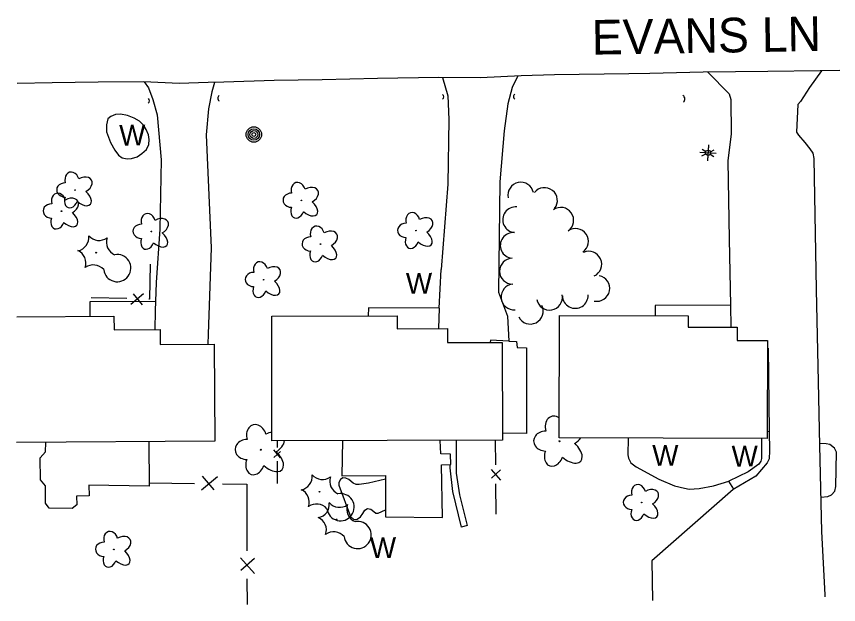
# Model space of a CAD drawing. Extents: x 588843 to 2552415, y 180129 to 269402.
# Drawn here: x 593448.9 to 593686.1, y 188818.1 to 188987.9 of the extents above; entities that cross this region are included whole.
import ezdxf

# ---------------------------------------------------------------- set-up
doc = ezdxf.new("R2010")
doc.units = 0
for name, color, linetype in [('Default', 7, 'Continuous'), ('E_BLD', 7, 'Continuous'), ('E_BLD_HvyDash', 7, 'Continuous'), ('E_DRN', 7, 'Continuous'), ('E_DWY', 7, 'Continuous'), ('E_FEN_P', 7, 'Continuous'), ('E_LAND_TreeLine_P', 7, 'Continuous'), ('E_LAND_Vegetation', 7, 'Continuous'), ('E_MISCPROP', 7, 'Continuous'), ('E_MISCPROP_ShtDash', 7, 'Continuous'), ('E_MISCPROP_YardLight', 7, 'Continuous'), ('E_PATH_Sidewalk', 7, 'Continuous'), ('E_RDWY', 7, 'Continuous'), ('E_RDWY_Text', 7, 'Continuous'), ('E_WAL', 7, 'Continuous'), ('E_WAL_Text', 7, 'Continuous')]:
    doc.layers.add(name, color=color, linetype=linetype)

# ---------------------------------------------------------------- blocks, each defined once
blk = doc.blocks.new('POLE')
at = {"layer": 'Default'}
for radius in [4.46, 3.35, 2.23, 1.12]:
    blk.add_circle((0, 0), radius, dxfattribs=at)
blk = doc.blocks.new('CULV2')
at = {"layer": 'E_DRN'}
blk.add_arc((19.7, 14.8), 24.6, 216.8699, 323.1301, dxfattribs=at)
blk = doc.blocks.new('W_29')
at = {"layer": 'E_WAL_Text'}
blk.add_text('W', height=12, dxfattribs=at).set_placement((-4.46, -6))
blk = doc.blocks.new('CTRE')
at = {"layer": 'Default'}
blk.add_circle((0, 0), 0.223, dxfattribs=at)
for centre, start, end in [((-11.97, 8.96), 280.2067, 5.9716), ((1.81, 14.92), 220.2113, 305.9762), ((13.83, 5.89), 160.2113, 245.9762), ((-13.83, -5.9), 340.2113, 65.9762), ((12.03, -9.04), 185.9272, 100.2511), ((-1.81, -14.93), 40.2113, 125.9762)]:
    blk.add_arc(centre, 7.87, start, end, dxfattribs=at)
blk = doc.blocks.new('DTRE')
at = {"layer": 'Default'}
blk.add_circle((-0.18, 0), 0.183, dxfattribs=at)
for centre, major_axis, ratio in [((-1.87, 5.32), (1.36, -4.98), 0.782863), ((4.06, 2.74), (-5.27, -2.93), 0.691916), ((-5.87, 0.15), (4.93, -0.12), 0.832022), ((-2.49, -5.24), (1.8, 4.86), 0.716896), ((3.54, -3.71), (-5.01, 4.58), 0.560249)]:
    blk.add_ellipse(centre, major_axis=major_axis, ratio=ratio, start_param=1.570796, end_param=4.712389, dxfattribs=at)
blk = doc.blocks.new('LITE')
at = {"layer": 'E_MISCPROP_YardLight'}
for p, q in [((-4, 0), (-1.5, 0)), ((-0.75, 1.3), (-2, 3.46)), ((0, -4.67), (0, 4.67)), ((0.75, 1.3), (2, 3.46)), ((1.5, 0), (4, 0)), ((-4.67, 0), (4.67, 0)), ((-2, -3.46), (-0.75, -1.3)), ((2, -3.46), (0.75, -1.3))]:
    blk.add_line(p, q, dxfattribs=at)
for radius in [1.5, 1.5, 1.5, 0.125]:
    blk.add_circle((0, 0), radius, dxfattribs=at)
blk = doc.blocks.new('U309')
at = {"layer": 'E_LAND_Vegetation'}
blk.add_circle((-0.09, 0.01), 0.128, dxfattribs=at)
for centre, major_axis, ratio, start_param, end_param in [((-1.31, 3.72), (0.99, -3.48), 0.782863, 2.378624, 4.712389), ((-4.07, 0.07), (3.45, -0.05), 0.832022, 1.570796, 4.712389), ((2.86, 1.95), (-3.67, -2.09), 0.691916, 1.570796, 2.149552), ((2.54, -2.56), (-3.54, 3.17), 0.560249, 1.570796, 4.712389), ((-1.67, -3.68), (1.23, 3.41), 0.716896, 1.570796, 4.712389)]:
    blk.add_ellipse(centre, major_axis=major_axis, ratio=ratio, start_param=start_param, end_param=end_param, dxfattribs=at)
blk = doc.blocks.new('U310')
at = {"layer": 'E_LAND_Vegetation'}
blk.add_circle((-0.09, 0.01), 0.128, dxfattribs=at)
for centre, major_axis, ratio, start_param, end_param in [((-1.31, 3.72), (0.99, -3.48), 0.782863, 1.570796, 4.712389), ((2.86, 1.95), (-3.67, -2.09), 0.691916, 4.26798, 4.712389), ((-4.07, 0.07), (3.45, -0.05), 0.832022, 1.570796, 4.712389), ((2.86, 1.95), (-3.67, -2.09), 0.691916, 1.570796, 2.664075), ((2.54, -2.56), (-3.54, 3.17), 0.560249, 1.570796, 4.712389), ((-1.67, -3.68), (1.23, 3.41), 0.716896, 1.570796, 4.712389)]:
    blk.add_ellipse(centre, major_axis=major_axis, ratio=ratio, start_param=start_param, end_param=end_param, dxfattribs=at)

msp = doc.modelspace()

# ---------------------------------------------------------------- linework, layer by layer
at = {"layer": 'E_BLD'}
msp.add_lwpolyline([(593449.02, 188901.2), (593477.07, 188901.39), (593477.09, 188897.46), (593490.38, 188897.55), (593490.41, 188893.21), (593505.96, 188893.31), (593506.14, 188865.23), (593448.94, 188864.86)], dxfattribs=at)
for points in [[(593589.17, 188865.54), (593522.66, 188865.42), (593522.59, 188901.39), (593558.77, 188901.45), (593558.78, 188897.75), (593573.29, 188897.77), (593573.3, 188893.79), (593589.11, 188893.81), (593589.17, 188865.54)], [(593665.56, 188866.06), (593605.53, 188866.22), (593605.62, 188901.56), (593642.76, 188901.47), (593642.75, 188898.19), (593656.92, 188898.15), (593656.91, 188894.34), (593665.64, 188894.32), (593665.56, 188866.06)]]:
    msp.add_lwpolyline(points, close=True, dxfattribs=at)
at = {"layer": 'E_BLD_HvyDash'}
for points in [[(593487.13, 188865.11), (593487.2, 188852.3), (593469.78, 188852.58), (593469.89, 188849.51), (593466.31, 188849.4), (593466.37, 188846.94), (593464.99, 188845.86), (593458.43, 188845.9), (593457.32, 188847.37), (593457.3, 188852.38), (593455.87, 188854.08), (593455.74, 188860.44), (593457.33, 188862.19), (593457.4, 188864.91)], [(593542.97, 188865.46), (593542.82, 188855.3), (593555.44, 188855.41), (593555.38, 188843.46), (593571.84, 188843.24), (593571.55, 188858.44), (593574.25, 188858.55), (593574.2, 188861.57), (593571.39, 188861.61), (593571.17, 188865.51)]]:
    msp.add_lwpolyline(points, dxfattribs=at)
at = {"layer": 'E_DWY'}
for points in [[(593648.45, 188971.81), (593654.58, 188965.55), (593655.1, 188963.97), (593655.19, 188954.04), (593654.18, 188946.23), (593654.56, 188923.59), (593654.95, 188904.52), (593655.09, 188898.16)], [(593681.18, 188972.18), (593677.75, 188967.41), (593675.13, 188963.32), (593674.42, 188962.5), (593674.02, 188954.45), (593674.55, 188953.63), (593676.42, 188951.52), (593677.82, 188949.7), (593678.69, 188948.44), (593679.01, 188946.88), (593679.7, 188909.1), (593680.25, 188882.45), (593680.67, 188864.06), (593681.25, 188839.17), (593682.17, 188820.92), (593682.21, 188820.38)], [(593571.85, 188970.24), (593573.41, 188964.97), (593573.71, 188958.14), (593573.4, 188939.49), (593571.49, 188914.81)], [(593593.63, 188970.75), (593592.01, 188967.42), (593590.74, 188962.68), (593589.64, 188954.89), (593588.43, 188940.19), (593588, 188908.27), (593590.64, 188901.41), (593591.03, 188894.12), (593585.67, 188894.4), (593585.64, 188893.81)], [(593485.78, 188969), (593487.04, 188967.33), (593488.26, 188963.93), (593489.5, 188959.47), (593490.73, 188946.46), (593490.3, 188926.46), (593489.23, 188911.09), (593488.95, 188902.89), (593488.91, 188897.54)], [(593506.08, 188968.86), (593505.28, 188966.11), (593504.39, 188961.19), (593503.72, 188953.7), (593505.16, 188921.1), (593504.25, 188896.21), (593504.2, 188893.3)], [(593570.91, 188903.65), (593570.76, 188897.77)], [(593665.63, 188892.15), (593665.87, 188892.15), (593666.13, 188868.21)], [(593666.13, 188868.21), (593666.23, 188862.44), (593666.08, 188860.22), (593665.52, 188859.02), (593662.28, 188855.13), (593655.75, 188851.3)], [(593655.75, 188851.3), (593632.26, 188830.71), (593632.42, 188819.28)]]:
    msp.add_lwpolyline(points, dxfattribs=at)
at = {"layer": 'E_FEN_P'}
for p, q in [((593485.56, 188907.78), (593481.91, 188904.74)), ((593485.33, 188904.67), (593482.7, 188907.78)), ((593525.15, 188860.48), (593523.19, 188862.73)), ((593523.19, 188860.59), (593525.11, 188862.28)), ((593585.93, 188857.08), (593588.62, 188854.03)), ((593588.6, 188856.96), (593586, 188854.63)), ((593502.29, 188851.19), (593506.91, 188855.1)), ((593502.56, 188855.16), (593505.94, 188851.22)), ((593513.61, 188831.6), (593517.6, 188827.04)), ((593517.59, 188831.4), (593513.71, 188827.95))]:
    msp.add_line(p, q, dxfattribs=at)
for points in [[(593487.48, 188916.38), (593487.31, 188906.3), (593487.11, 188906.31)], [(593480.75, 188906.45), (593470.47, 188906.67)], [(593524.24, 188863.49), (593524.24, 188865.42)], [(593587.11, 188865.54), (593587.16, 188858.44)], [(593524.25, 188853.03), (593524.24, 188859.49)], [(593487.2, 188853.24), (593500.3, 188853.06)], [(593508.41, 188852.94), (593515.4, 188852.84), (593515.41, 188846.72)], [(593587.19, 188852.99), (593587.25, 188844.19)], [(593515.41, 188846.72), (593515.44, 188833.62)], [(593515.46, 188825.51), (593515.48, 188818.1)]]:
    msp.add_lwpolyline(points, dxfattribs=at)
at = {"layer": 'E_LAND_TreeLine_P'}
for centre, start, end in [((593594.45, 188936.31), 11.4269, 191.4269), ((593601.3, 188934.75), 321.8328, 141.8328), ((593592.96, 188929.2), 84.629, 264.629), ((593605.99, 188929.04), 304.9676, 124.9676), ((593610.25, 188922.94), 304.9676, 124.9676), ((593592.27, 188921.79), 84.629, 264.629), ((593614.09, 188916.37), 294.1506, 114.1506), ((593592.05, 188914.35), 90.5591, 270.5591), ((593616.39, 188909.38), 258.8482, 78.8482), ((593592.5, 188906.92), 94.9116, 274.9116), ((593602.75, 188906.85), 189.8849, 9.8849), ((593610.17, 188907.35), 182.1122, 2.1122), ((593597.19, 188902.82), 206.4168, 26.4168)]:
    msp.add_arc(centre, 3.72, start, end, dxfattribs=at)
at = {"layer": 'E_MISCPROP_ShtDash'}
msp.add_lwpolyline([(593591.03, 188894.12), (593593.26, 188894.03), (593593.4, 188892.3), (593596.15, 188892.23), (593596.09, 188867.46), (593589.16, 188867.55)], dxfattribs=at)
at = {"layer": 'E_PATH_Sidewalk'}
for points in [[(593489.04, 188905.6), (593470.09, 188905.53), (593470.14, 188901.34)], [(593570.91, 188903.65), (593550.47, 188903.73), (593550.4, 188901.44)], [(593654.95, 188904.56), (593633.25, 188904.47), (593633.23, 188901.49)], [(593665.57, 188868.1), (593666.13, 188868.14)], [(593575.84, 188865.52), (593575.79, 188856.03), (593576.74, 188849.79), (593579.01, 188840.94), (593577.36, 188840.48), (593574.84, 188850.76), (593574.07, 188857.56), (593574.1, 188858.55)], [(593660.03, 188856.38), (593654.52, 188853.73)], [(593655.92, 188851.4), (593654.52, 188853.73)]]:
    msp.add_lwpolyline(points, dxfattribs=at)
at = {"layer": 'E_RDWY'}
msp.add_lwpolyline([(593686.53, 188972.34), (593680.81, 188972.17), (593665.71, 188972.05), (593647.09, 188971.79), (593631.73, 188971.46), (593625.62, 188971.32), (593604.22, 188971.01), (593594.56, 188970.8), (593582.79, 188970.18), (593570.82, 188970.24), (593553.14, 188969.97), (593537.13, 188969.6), (593523.28, 188969.45), (593508.76, 188968.92), (593504.28, 188968.82), (593495.92, 188968.56), (593485.67, 188969), (593472.52, 188968.91), (593459.27, 188968.76), (593449.17, 188968.57)], dxfattribs=at)
at = {"layer": 'E_WAL'}
msp.add_lwpolyline([(593482.94, 188958.5), (593481.01, 188959.27), (593478.96, 188959.74), (593477.53, 188959.6), (593476.15, 188959.05), (593475.33, 188958.32), (593474.88, 188956.65), (593474.94, 188954.57), (593476.04, 188951.52), (593477.3, 188949.27), (593478.37, 188947.89), (593479.49, 188947.09), (593480.86, 188946.8), (593482.15, 188946.88), (593483.76, 188947.37), (593485.14, 188948.34), (593486.49, 188949.53), (593487.14, 188950.94), (593487.2, 188952.4), (593487, 188953.75), (593486.36, 188955.3), (593485.63, 188956.54), (593484.43, 188957.68), (593482.94, 188958.5)], close=True, dxfattribs=at)
for points in [[(593570.91, 188903.65), (593571.49, 188914.81)], [(593625.42, 188866.16), (593625.37, 188861.33), (593625.49, 188860.34), (593626.16, 188858.99), (593627.77, 188857.87), (593634.26, 188854.34), (593638.82, 188852.42), (593641.72, 188851.68), (593643.06, 188851.39), (593645.94, 188851.64), (593650.04, 188852.34), (593654.52, 188853.73)], [(593663.94, 188866.06), (593663.88, 188860.24), (593663.73, 188859.48), (593663.14, 188858.63), (593660.03, 188856.38)], [(593681.02, 188849.14), (593683.01, 188849.31), (593684.15, 188849.74), (593685.09, 188850.83), (593685.39, 188852.17), (593685.53, 188862.13), (593685.01, 188863.21), (593683.66, 188864.27), (593682.58, 188864.51), (593680.66, 188864.6)], [(593555.43, 188854.29), (593550.48, 188853.19), (593547.85, 188852.79), (593546.94, 188852.76), (593546.12, 188853.12), (593544.83, 188854.2), (593543.96, 188854.62), (593543.08, 188854.65), (593542.43, 188854.21), (593541.96, 188853.36), (593541.96, 188852.57), (593545.36, 188843.48), (593546.3, 188842.66), (593547.2, 188842.78), (593548.2, 188843.42), (593548.88, 188844.38), (593549.47, 188845.32), (593550.2, 188845.87), (593551.19, 188845.69), (593552.07, 188844.99), (593552.66, 188844.52), (593553.33, 188844.52), (593555.39, 188845.45)]]:
    msp.add_lwpolyline(points, dxfattribs=at)

# ---------------------------------------------------------------- block references
at = {"layer": 'E_DRN'}
for p, xscale, yscale, rotation in [((593507.45, 188965.04), 0.03871633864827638, 0.03871633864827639, -92.35085353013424), ((593571.9, 188963.99), 0.035711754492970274, 0.03571175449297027, 89.85174463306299), ((593592.76, 188965.49), 0.03722949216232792, 0.03722949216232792, -92.43886540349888), ((593641.37, 188963.17), 0.049193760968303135, 0.04919376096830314, 93.31997390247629), ((593486.94, 188962.84), 0.0342560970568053, 0.03425609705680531, 87.36219173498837)]:
    msp.add_blockref('CULV2', p, dxfattribs=dict(at, xscale=xscale, yscale=yscale, rotation=rotation))
at = {"layer": 'E_LAND_Vegetation', "xscale": 0.4999999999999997, "yscale": 0.4999999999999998, "rotation": 0.577990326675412}
for name, p in [('DTRE', (593465.95, 188937.78)), ('DTRE', (593531.25, 188934.8)), ('DTRE', (593462.04, 188931.7)), ('DTRE', (593487.97, 188925.83)), ('DTRE', (593564.29, 188926.08)), ('DTRE', (593536.75, 188922.19)), ('CTRE', (593471.96, 188919.7)), ('DTRE', (593520.35, 188911.9)), ('CTRE', (593536.39, 188850.68)), ('DTRE', (593629.42, 188847.57)), ('CTRE', (593541.32, 188842.64)), ('DTRE', (593477.13, 188834.02))]:
    msp.add_blockref(name, p, dxfattribs=at)
at = {"layer": 'E_LAND_Vegetation'}
for name, p in [('U309', (593605.69, 188865.23)), ('U310', (593519.52, 188862.79))]:
    msp.add_blockref(name, p, dxfattribs=at)
at = {"layer": 'E_MISCPROP', "xscale": 0.4999999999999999, "yscale": 0.4999999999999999, "rotation": -27.779860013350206}
msp.add_blockref('POLE', (593517.44, 188953.82), dxfattribs=at)
at = {"layer": 'E_MISCPROP_YardLight', "xscale": 0.4999999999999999, "yscale": 0.5, "rotation": -93.51471597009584}
msp.add_blockref('LITE', (593648.48, 188948.53), dxfattribs=at)
at = {"layer": 'E_WAL_Text', "xscale": 0.4999999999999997, "yscale": 0.4999999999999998, "rotation": 0.577990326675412}
for p in [(593480.82, 188953.62), (593563.56, 188910.83), (593634.63, 188861.16), (593657.53, 188860.95), (593553.16, 188834.51)]:
    msp.add_blockref('W_29', p, dxfattribs=at)

# ---------------------------------------------------------------- texts
at = {"layer": 'E_RDWY_Text'}
msp.add_text('EVANS LN', height=10, rotation=0.9169, dxfattribs=at).set_placement((593615.01, 188976.87))

doc.saveas('drawing.dxf')
